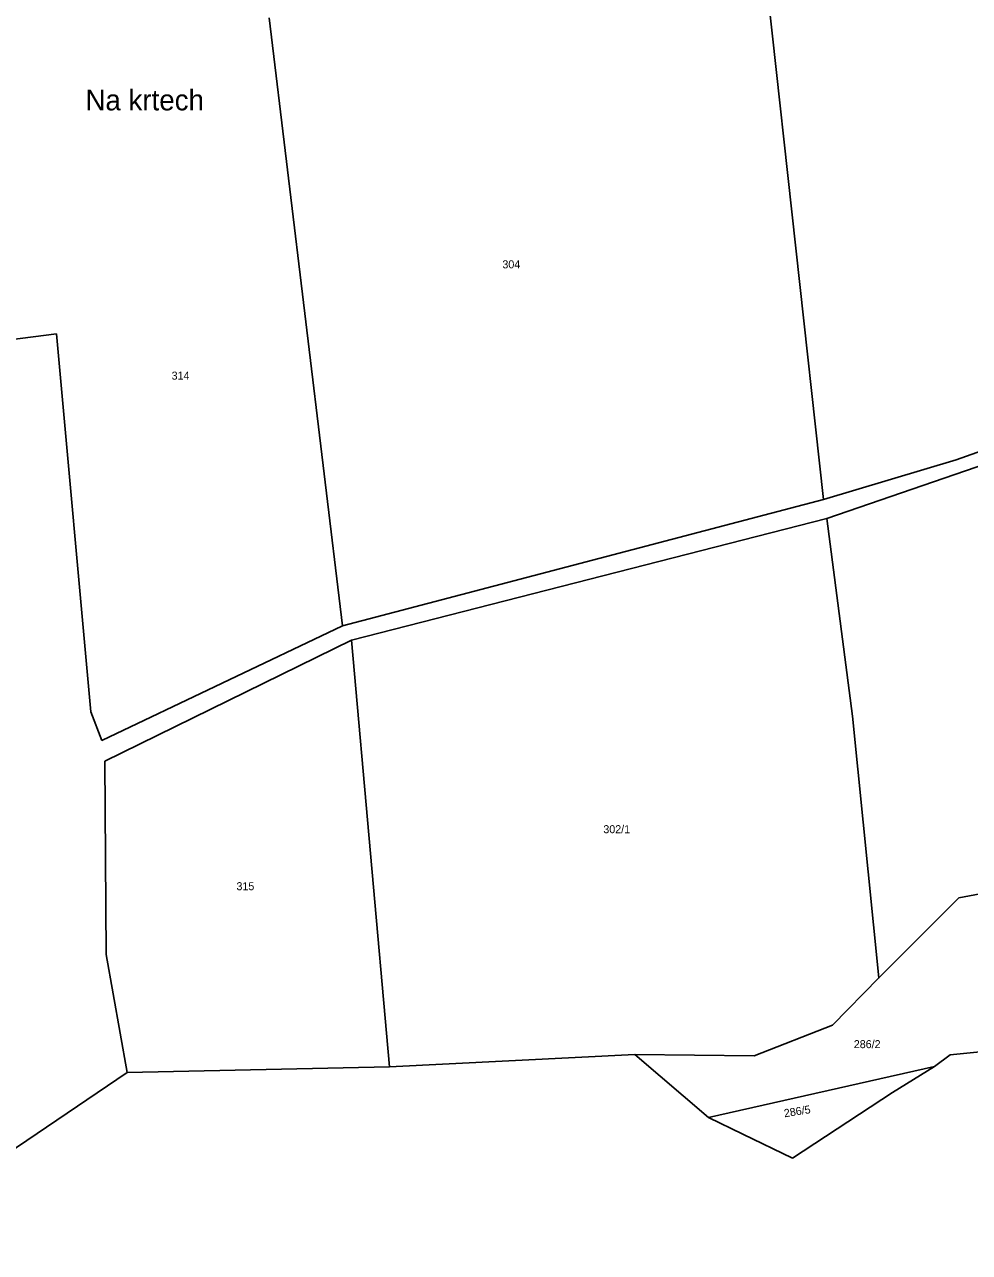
# Model space of a CAD drawing. Extents: x -645290 to -643454, y -1064771 to -1062356.
# Drawn here: x -644411.4 to -644210.6, y -1064092.7 to -1063831.9 of the extents above; entities that cross this region are included whole.
import ezdxf
from ezdxf.enums import TextEntityAlignment as Align

# ---------------------------------------------------------------- set-up
doc = ezdxf.new("R2010")
doc.units = 0
doc.header["$LTSCALE"] = 0.68
doc.layers.add('1', color=7, linetype='Continuous', lineweight=25)
doc.layers.add('7', color=7, linetype='Continuous', lineweight=13)
doc.layers.add('2', color=7, linetype='Continuous')

msp = doc.modelspace()

# ---------------------------------------------------------------- linework, layer by layer
at = {"layer": '1'}
for p, q in [((-644241.61, -1063932.75), (-644256.17, -1063800.7)), ((-644343.83, -1063959.61), (-644359.35, -1063830.45)), ((-644446.1, -1063902.87), (-644404.58, -1063897.62)), ((-644404.58, -1063897.62), (-644397.27, -1063977.87)), ((-644147.42, -1063900.81), (-644213.45, -1063924.36)), ((-644147.41, -1063904.66), (-644240.87, -1063936.79)), ((-644213.45, -1063924.36), (-644241.61, -1063932.75)), ((-644343.83, -1063959.61), (-644241.61, -1063932.75)), ((-644341.86, -1063962.67), (-644240.87, -1063936.79)), ((-644240.87, -1063936.79), (-644235.44, -1063978.75)), ((-644394.92, -1063983.95), (-644343.83, -1063959.61)), ((-644394.32, -1063988.36), (-644341.86, -1063962.67)), ((-644333.82, -1064053.27), (-644341.86, -1063962.67)), ((-644394.92, -1063983.95), (-644397.27, -1063977.87)), ((-644394.32, -1063988.36), (-644394.02, -1064029.42)), ((-644229.84, -1064034.38), (-644212.87, -1064017.33)), ((-644212.87, -1064017.33), (-644208.32, -1064016.48)), ((-644394.02, -1064029.42), (-644389.56, -1064054.44)), ((-644256.36, -1064050.94), (-644239.69, -1064044.4)), ((-644333.82, -1064053.27), (-644281.7, -1064050.63)), ((-644281.7, -1064050.63), (-644256.36, -1064050.94)), ((-644281.7, -1064050.63), (-644266.01, -1064064)), ((-644218.01, -1064053.2), (-644214.67, -1064050.68)), ((-644214.67, -1064050.68), (-644208.31, -1064050.09)), ((-644389.56, -1064054.44), (-644333.82, -1064053.27)), ((-644218.01, -1064053.2), (-644266.01, -1064064)), ((-644226.94, -1064058.72), (-644218.01, -1064053.2)), ((-644446.09, -1064092.67), (-644389.56, -1064054.44)), ((-644248.22, -1064072.66), (-644226.94, -1064058.72)), ((-644266.01, -1064064), (-644258.74, -1064067.54)), ((-644258.74, -1064067.54), (-644248.22, -1064072.66))]:
    msp.add_line(p, q, dxfattribs=at)
msp.add_lwpolyline([(-644239.69, -1064044.4), (-644229.84, -1064034.38), (-644235.44, -1063978.75)], dxfattribs=at)

# ---------------------------------------------------------------- texts
at = {"layer": '2'}
for s, p in [('304', (-644309.83, -1063883.675)), ('314', (-644380.11, -1063907.314)), ('302/1', (-644288.38, -1064003.635)), ('315', (-644366.33, -1064015.745)), ('286/2', (-644235.17, -1064049.285))]:
    msp.add_text(s, height=1.7, dxfattribs=at).set_placement(p)
msp.add_text('286/5', height=1.7, rotation=9, dxfattribs=at).set_placement((-644247.065, -1064063.5286), align=Align.CENTER)
at = {"layer": '7'}
msp.add_text('Na krtech', height=4.4, dxfattribs=at).set_placement((-644398.42, -1063850.13))

doc.saveas('drawing.dxf')
